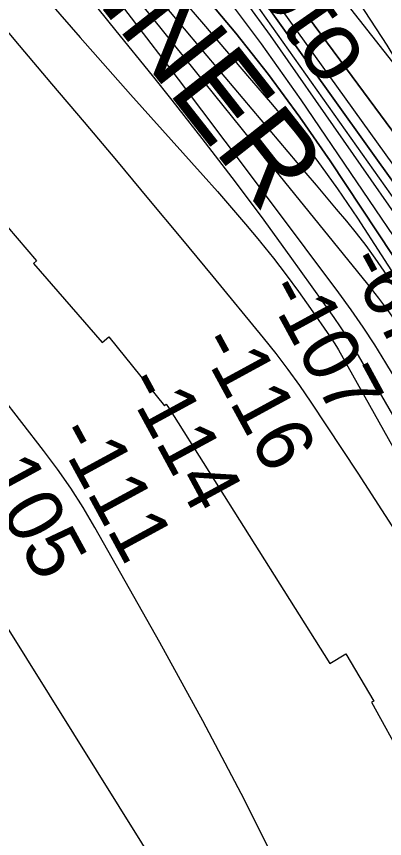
# Model space of a CAD drawing. Extents: x 3625074 to 3663148, y 511451 to 537151.
# Drawn here: x 3631539 to 3631975, y 530470 to 531443 of the extents above; entities that cross this region are included whole.
import ezdxf

# ---------------------------------------------------------------- set-up
doc = ezdxf.new("R2010")
doc.units = 0
for name, color, linetype in [('V-RIVR-EDGE', 7, 'Continuous'), ('V-RIVR-IDEN', 7, 'Continuous'), ('V-RIVR-RANG', 7, 'Continuous'), ('V-RRAP-RVMT', 7, 'Continuous'), ('V-RRAP-RVMT-IDEN', 7, 'Continuous'), ('V-TOPO-DPTH', 7, 'Continuous'), ('V-TOPO-MAJR', 7, 'Continuous'), ('V-TOPO-MINR', 7, 'Continuous'), ('V-TOPO-WATR', 7, 'Continuous')]:
    doc.layers.add(name, color=color, linetype=linetype)

msp = doc.modelspace()

# ---------------------------------------------------------------- linework, layer by layer
at = {"layer": 'V-RIVR-EDGE'}
msp.add_lwpolyline([(3632616.45, 530359.53), (3632551.25, 530504.91), (3632526.89, 530565.01), (3632500.05, 530613.49), (3632468.3, 530660.74), (3632424.34, 530720.9), (3632375.54, 530808.64), (3632335.88, 530879.81), (3632296.85, 530951.6), (3632193.69, 531111.16), (3632160.14, 531171.29), (3632085.58, 531248.07), (3632017.19, 531345.66), (3631978.14, 531409.48), (3631886.57, 531550.02), (3631859.08, 531580.73), (3631768.66, 531690.02), (3631650.74, 531826.33), (3631587.8, 531891.44), (3631527.91, 531958.37), (3631408.17, 532100.21), (3631361.11, 532147.51), (3631269.52, 532277.63)], dxfattribs=at)
at = {"layer": 'V-RRAP-RVMT'}
for p, q in [((3631491.11, 531236.27), (3631562.55, 531153.96)), ((3631562.55, 531153.96), (3631558.89, 531150.79)), ((3631558.89, 531150.79), (3631640.22, 531057.15)), ((3631640.22, 531057.15), (3631648.05, 531064.02)), ((3631648.05, 531064.02), (3631714.02, 530982.5)), ((3631714.02, 530982.5), (3631716.38, 530984.41)), ((3631716.38, 530984.41), (3631719.13, 530980.53)), ((3631719.13, 530980.53), (3631910.42, 530677.11)), ((3631910.42, 530677.11), (3631929.16, 530688.54)), ((3631929.16, 530688.54), (3631962.33, 530632.63)), ((3631962.33, 530632.63), (3631959.86, 530631.21)), ((3631959.86, 530631.21), (3632045.41, 530475.68))]:
    msp.add_line(p, q, dxfattribs=at)
at = {"layer": 'V-TOPO-DPTH'}
for points in [[(3632543.7, 530234.98), (3632288.13, 530709.93), (3632249.59, 530780.28), (3632210.36, 530850.23), (3632170.09, 530919.59), (3632129.13, 530988.56), (3632075.85, 531076.75), (3632060.76, 531101.16), (3632045.36, 531125.37), (3632029.47, 531149.27), (3632013.26, 531172.95), (3631839.92, 531420.96), (3631782.38, 531500.17), (3631722.97, 531577.9), (3631660.77, 531653.41), (3631596.71, 531727.44), (3631484.46, 531852.47)], [(3632543.7, 530234.98), (3632288.13, 530709.93), (3632249.59, 530780.28), (3632210.36, 530850.23), (3632170.09, 530919.59), (3632129.13, 530988.56), (3632075.85, 531076.75), (3632060.76, 531101.16), (3632045.36, 531125.37), (3632029.47, 531149.27), (3632013.26, 531172.95), (3631839.92, 531420.96), (3631782.38, 531500.17), (3631722.97, 531577.9), (3631660.77, 531653.41), (3631596.71, 531727.44), (3631484.46, 531852.47)], [(3631537.82, 531844.51), (3631599.86, 531769.8), (3631660.61, 531694.07), (3631719.43, 531616.85), (3631776.96, 531538.61), (3632024.61, 531192.8), (3632044.79, 531164.07), (3632064.61, 531135.09), (3632083.88, 531105.76), (3632102.8, 531076.19), (3632121.27, 531046.33), (3632139.52, 531016.33), (3632157.42, 530986.13), (3632175.09, 530955.78), (3632433.54, 530506.03), (3632457.62, 530464.33)], [(3632457.62, 530464.33), (3632433.54, 530506.03), (3632175.09, 530955.78), (3632157.42, 530986.13), (3632139.52, 531016.33), (3632121.27, 531046.33), (3632102.8, 531076.19), (3632083.88, 531105.76), (3632064.61, 531135.09), (3632044.79, 531164.07), (3632024.61, 531192.8), (3631776.96, 531538.61), (3631719.43, 531616.85), (3631660.61, 531694.07), (3631599.86, 531769.8), (3631537.82, 531844.51)], [(3631522.92, 531775.34), (3631545.73, 531749.29), (3631568.57, 531723.26), (3631591.47, 531697.28), (3631614.4, 531671.33), (3631676.41, 531601.3), (3631729.15, 531539.41), (3631780.25, 531476.24), (3631828.9, 531411.17), (3631875.92, 531344.83), (3632008.01, 531150.68), (3632019, 531134.17), (3632029.75, 531117.51), (3632040.16, 531100.63), (3632050.33, 531083.6), (3632159.57, 530896.41), (3632223.25, 530785.16), (3632285.67, 530673.23), (3632346.22, 530560.27), (3632405.51, 530446.62)], [(3631522.92, 531775.34), (3631545.73, 531749.29), (3631568.57, 531723.26), (3631591.47, 531697.28), (3631614.4, 531671.33), (3631676.41, 531601.3), (3631729.15, 531539.41), (3631780.25, 531476.24), (3631828.9, 531411.17), (3631875.92, 531344.83), (3632008.01, 531150.68), (3632019, 531134.17), (3632029.75, 531117.51), (3632040.16, 531100.63), (3632050.33, 531083.6), (3632159.57, 530896.41), (3632223.25, 530785.16), (3632285.67, 530673.23), (3632346.22, 530560.27), (3632405.51, 530446.62)], [(3632410.92, 530404.27), (3632368.99, 530484.76), (3632325.79, 530564.57), (3632281.75, 530643.93), (3632029.99, 531089.34), (3632023.65, 531100.29), (3632017.14, 531111.15), (3632010.41, 531121.87), (3632003.52, 531132.49), (3631910.55, 531272.55), (3631874.81, 531324.14), (3631837.75, 531374.73), (3631798.71, 531423.81), (3631758.36, 531471.89), (3631751.02, 531480.29), (3631713.38, 531523.44), (3631675.8, 531566.63), (3631638.29, 531609.88), (3631600.82, 531653.18), (3631563.54, 531696.63), (3631526.46, 531740.25)], [(3631526.46, 531740.25), (3631563.54, 531696.63), (3631600.82, 531653.18), (3631638.29, 531609.88), (3631675.8, 531566.63), (3631713.38, 531523.44), (3631751.02, 531480.29), (3631758.36, 531471.89), (3631798.71, 531423.81), (3631837.75, 531374.73), (3631874.81, 531324.14), (3631910.55, 531272.55), (3632003.52, 531132.49), (3632010.41, 531121.87), (3632017.14, 531111.15), (3632023.65, 531100.29), (3632029.99, 531089.34), (3632281.75, 530643.93), (3632325.79, 530564.57), (3632368.99, 530484.76), (3632410.92, 530404.27)], [(3631883.87, 531443.64), (3631929.94, 531381.36), (3631983.68, 531308.77), (3632002.94, 531282.84), (3632022.25, 531256.93), (3632041.63, 531231.09), (3632061.06, 531205.28), (3632089.16, 531168.06), (3632094.5, 531160.83), (3632099.72, 531153.52), (3632104.78, 531146.09), (3632109.73, 531138.58), (3632238.18, 530938.8), (3632305.56, 530830.36), (3632370.65, 530720.62), (3632432.33, 530608.92), (3632491.72, 530495.92), (3632622.49, 530237.47)], [(3632622.49, 530237.47), (3632491.72, 530495.92), (3632432.33, 530608.92), (3632370.65, 530720.62), (3632305.56, 530830.36), (3632238.18, 530938.8), (3632109.73, 531138.58), (3632104.78, 531146.09), (3632099.72, 531153.52), (3632094.5, 531160.83), (3632089.16, 531168.06), (3632061.06, 531205.28), (3632041.63, 531231.09), (3632022.25, 531256.93), (3632002.94, 531282.84), (3631983.68, 531308.77), (3631929.94, 531381.36), (3631883.87, 531443.64)]]:
    msp.add_lwpolyline(points, dxfattribs=at)
at = {"layer": 'V-TOPO-MAJR'}
for points in [[(3630575.52, 532635.77), (3630932.4, 532234.78), (3630984.68, 532175.51), (3631036.61, 532115.95), (3631088.01, 532055.93), (3631139.07, 531995.61), (3631231.06, 531885.95), (3631235.84, 531880.21), (3631240.59, 531874.46), (3631245.3, 531868.68), (3631249.99, 531862.87), (3631440.64, 531625.25), (3631497.56, 531555.53), (3631555.24, 531486.47), (3631614.1, 531418.39), (3631673.72, 531350.97), (3631759.91, 531255.18), (3631776.9, 531236.05), (3631793.73, 531216.78)], [(3632426.79, 530341.94), (3632014.01, 531094.04), (3632010.6, 531100.09), (3632007.11, 531106.09), (3632003.48, 531112), (3631999.77, 531117.87), (3631943.48, 531204.6), (3631919.93, 531239.33), (3631895.46, 531273.36), (3631869.63, 531306.38), (3631842.89, 531338.7), (3631815.48, 531370.54), (3631788.1, 531402.39), (3631760.76, 531434.28), (3631733.45, 531466.2), (3631681.3, 531527.23), (3631628.16, 531589.85), (3631575.3, 531652.73), (3631522.89, 531715.97)], [(3631793.73, 531216.78), (3631810.33, 531197.31), (3631826.76, 531177.7), (3631827.9, 531176.32), (3631843.39, 531157.1), (3631858.55, 531137.64), (3631873.21, 531117.79), (3631887.54, 531097.7), (3631910.04, 531065.29), (3631912.81, 531061.17), (3631915.5, 531057), (3631918.07, 531052.76), (3631920.56, 531048.47), (3632307.06, 530359.44)], [(3631714.36, 530421.9), (3631469.78, 530812.03)]]:
    msp.add_lwpolyline(points, dxfattribs=at)
at = {"layer": 'V-TOPO-MINR'}
for points in [[(3630732.53, 532396.61), (3631157.42, 531885.48), (3631175.78, 531863.15), (3631193.96, 531840.68), (3631211.9, 531818.01), (3631229.66, 531795.21), (3631279.63, 531730.33), (3631322.16, 531675.82), (3631365.14, 531621.66), (3631408.79, 531568.04), (3631452.9, 531514.79), (3631465.33, 531499.97), (3631503.59, 531454.43), (3631541.91, 531408.93), (3631580.31, 531363.51), (3631618.77, 531318.13), (3631657.17, 531272.7), (3631695.42, 531227.16)], [(3632559.67, 530244.33), (3632231.17, 530835.19), (3632203, 530885.08), (3632174.39, 530934.71), (3632145.12, 530983.96), (3632115.42, 531032.95), (3632090.85, 531072.87), (3632072.83, 531101.53), (3632054.43, 531129.95), (3632035.49, 531157.99), (3632016.18, 531185.8), (3631821.49, 531460.36), (3631758.92, 531545.36), (3631694.41, 531628.79), (3631626.98, 531709.88), (3631557.61, 531789.41), (3631421.73, 531939.72)], [(3632638.07, 530284.04), (3632282.33, 530956.28), (3632261.57, 530994.44), (3632240.23, 531032.27), (3632218.03, 531069.6), (3632195.25, 531106.6), (3632188.08, 531117.96), (3632168, 531148.71), (3632147.32, 531179.03), (3632125.74, 531208.71), (3632103.55, 531237.97), (3632003.82, 531365.44), (3631931, 531457.85), (3631857.75, 531549.93), (3631783.87, 531641.5), (3631709.56, 531732.72), (3631576.94, 531894.4), (3631563.25, 531911.29), (3631549.69, 531928.3), (3631536.34, 531945.46)], [(3632516.19, 530411.98), (3632478.37, 530481.03), (3632438.73, 530549.05), (3632397.88, 530616.39), (3632260.12, 530836.83), (3632233.67, 530879.6), (3632207.48, 530922.54), (3632181.71, 530965.72), (3632156.2, 531009.06), (3632119.12, 531072.74), (3632112.28, 531084.32), (3632105.35, 531095.85), (3632098.29, 531107.29), (3632091.13, 531118.67), (3632083.82, 531129.95), (3632076.37, 531141.15), (3632068.74, 531152.22), (3632060.98, 531163.2), (3631703.64, 531660.1), (3631660.32, 531719.33), (3631616.36, 531778.07), (3631571.46, 531836.1), (3631525.92, 531893.64)], [(3632543.7, 530234.98), (3632288.13, 530709.93), (3632249.59, 530780.28), (3632210.36, 530850.23), (3632170.09, 530919.59), (3632129.13, 530988.56), (3632075.85, 531076.75), (3632060.76, 531101.16), (3632045.36, 531125.37), (3632029.47, 531149.27), (3632013.26, 531172.95), (3631839.92, 531420.96), (3631782.38, 531500.17), (3631722.97, 531577.9), (3631660.77, 531653.41), (3631596.71, 531727.44), (3631484.46, 531852.47)], [(3632457.62, 530464.33), (3632433.54, 530506.03), (3632175.09, 530955.78), (3632157.42, 530986.13), (3632139.52, 531016.33), (3632121.27, 531046.33), (3632102.8, 531076.19), (3632083.88, 531105.76), (3632064.61, 531135.09), (3632044.79, 531164.07), (3632024.61, 531192.8), (3631776.96, 531538.61), (3631719.43, 531616.85), (3631660.61, 531694.07), (3631599.86, 531769.8), (3631537.82, 531844.51)], [(3632441.1, 530158.13), (3632226.62, 530590.72), (3632184.22, 530673.57), (3632140.45, 530755.68), (3632094.61, 530836.65), (3632047.4, 530916.86), (3631976.8, 531033.43), (3631963.55, 531054.59), (3631949.9, 531075.47), (3631935.64, 531095.94), (3631920.97, 531116.14), (3631841.1, 531222.77), (3631786.05, 531295.96), (3631730.8, 531369.01), (3631675.25, 531441.83), (3631619.51, 531514.5), (3631371.74, 531836.21)], [(3632357.04, 530434.52), (3632307.38, 530529.74), (3632257.11, 530624.63), (3632206.44, 530719.31), (3632002.42, 531097.6), (3632001.1, 531099.99), (3631999.73, 531102.36), (3631998.31, 531104.7), (3631996.86, 531107.02), (3631974.55, 531141.68), (3631964.2, 531157.07), (3631953.46, 531172.16), (3631942.12, 531186.82), (3631930.39, 531201.18), (3631918.36, 531215.32), (3631906.35, 531229.47), (3631894.35, 531243.63), (3631882.35, 531257.81), (3631764.75, 531396.94), (3631694.28, 531480.94), (3631624.23, 531565.3), (3631554.82, 531650.17), (3631485.83, 531735.39)], [(3632410.92, 530404.27), (3632368.99, 530484.76), (3632325.79, 530564.57), (3632281.75, 530643.93), (3632029.99, 531089.34), (3632023.65, 531100.29), (3632017.14, 531111.15), (3632010.41, 531121.87), (3632003.52, 531132.49), (3631910.55, 531272.55), (3631874.81, 531324.14), (3631837.75, 531374.73), (3631798.71, 531423.81), (3631758.36, 531471.89), (3631751.02, 531480.29), (3631713.38, 531523.44), (3631675.8, 531566.63), (3631638.29, 531609.88), (3631600.82, 531653.18), (3631563.54, 531696.63), (3631526.46, 531740.25)], [(3632451.32, 530187.63), (3632048.75, 530982.57), (3632038.72, 531001.59), (3632028.29, 531020.39), (3632017.26, 531038.84), (3632005.83, 531057.05), (3631993.82, 531074.9), (3631981.44, 531092.47), (3631968.51, 531109.65), (3631955.22, 531126.56), (3631827.98, 531283.29), (3631751.01, 531378.55), (3631674.33, 531474.03), (3631598.09, 531569.86), (3631522.15, 531665.93)], [(3631613.66, 531479.57), (3631656.68, 531426.54), (3631699.52, 531373.37), (3631722.75, 531344.38), (3631758.67, 531298.82), (3631794.08, 531252.87), (3631828.74, 531206.36), (3631862.9, 531159.46), (3631914.92, 531086.82), (3631922.53, 531075.86), (3631929.92, 531064.76), (3631936.99, 531053.44), (3631943.85, 531041.99), (3632141.84, 530699.97), (3632195.35, 530605.17), (3632247.47, 530509.64), (3632297.5, 530413)], [(3631695.42, 531227.16), (3631733.48, 531181.45), (3631771.39, 531135.62), (3631831.24, 531062.95), (3631846.06, 531044.38), (3631860.49, 531025.53), (3631874.34, 531006.23), (3631887.79, 530986.65), (3631943.61, 530902.69), (3631983.83, 530840.4), (3632022.94, 530777.44), (3632060.37, 530713.47), (3632096.69, 530648.82), (3632362.74, 530160.17)], [(3631856.05, 530421.19), (3631809.08, 530515.86), (3631759.74, 530609.31), (3631708.83, 530701.96), (3631631.67, 530838.26), (3631617.64, 530861.81), (3631602.94, 530884.92), (3631587.23, 530907.36), (3631570.86, 530929.35), (3631467.5, 531061.93)]]:
    msp.add_lwpolyline(points, dxfattribs=at)
at = {"layer": 'V-TOPO-WATR'}
msp.add_lwpolyline([(3632622.49, 530237.47), (3632491.72, 530495.92), (3632432.33, 530608.92), (3632370.65, 530720.62), (3632305.56, 530830.36), (3632238.18, 530938.8), (3632109.73, 531138.58), (3632104.78, 531146.09), (3632099.72, 531153.52), (3632094.5, 531160.83), (3632089.16, 531168.06), (3632061.06, 531205.28), (3632041.63, 531231.09), (3632022.25, 531256.93), (3632002.94, 531282.84), (3631983.68, 531308.77), (3631929.94, 531381.36), (3631883.87, 531443.64)], dxfattribs=at)

# ---------------------------------------------------------------- texts
at = {"layer": 'V-RIVR-IDEN'}
msp.add_text('Photo', height=83, rotation=304.83392, dxfattribs=at).set_placement((3631738.06, 531594.9))
at = {"layer": 'V-RIVR-RANG'}
for s, p in [('-67', (3631928.1, 531152.78)), ('-107', (3631832.31, 531119.61)), ('-116', (3631752.64, 531056.78)), ('-114', (3631664.79, 531009.01)), ('-111', (3631583.36, 530949.42)), ('-105', (3631480.9, 530928.54))]:
    msp.add_text(s, height=67, rotation=298.52453, dxfattribs=at).set_placement(p)
at = {"layer": 'V-RRAP-RVMT-IDEN'}
msp.add_text('KENNER', height=100, rotation=308.19718, dxfattribs=at).set_placement((3631487.33, 531646.67))

doc.saveas('drawing.dxf')
